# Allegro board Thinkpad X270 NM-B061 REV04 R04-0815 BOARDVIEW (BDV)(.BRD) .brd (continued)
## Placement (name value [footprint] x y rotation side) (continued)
R908  10K_0201_5%  [R_0201]  269.68 68.63 270 top
R951  10K_0201_5%  [R_0201]  283.45 47.74 180 top
R1119  0_0402_5%  [R_0402]  105.49 78.99 0 top
R1219  2.2K_0201_5%  [R_0201]  283.64 57.85 180 top
R1235  0_0201_5%  [R_0201]  267.43 68.03 90 top
R1236  0_0201_5%  [R0201_SHORT]  268.59 68.05 90 top
R1237  0_0201_5%  [R0201_SHORT]  266.9 67.17 180 top
R1238  0_0201_5%  [R0201_SHORT]  266.85 68.05 90 top
R1239  10K_0201_5%  [R_0201]  266.32 66.48 0 top
R1867  10K_0201_5%  [R_0201]  285.87 49.39 180 bottom
R1868  4.7K_0201_5%  [R_0201]  281.22 46.75 0 top
R1869  100K_0201_5%  [R_0201]  282.5 46.11 90 top
R1875  4.7K_0402_5%  [R_0402]  35.39 70.19 90 top
R1877  4.7K_0402_5%  [R_0402]  35.8 73.34 0 top
R1897  4.7K_0402_5%  [R_0402]  36.26 71.11 270 top
R1899  4.7K_0402_5%  [R_0402]  36.71 72.45 180 top
R2378  2.2K_0201_5%  [R_0201]  50.95 72.45 0 top
R2379  2.2K_0201_5%  [R_0201]  50.95 71.82 0 top
R2481  22K_0201_5%  [R_0201]  283.11 46.11 90 top
R2500  4.7K_0402_5%  [R_0402]  46.92 74.79 90 top
R2512  27K_0201_5%  [R_0201]  37.4 66.54 180 top
R2515  4.99K_0201_1%  [R_0201]  46.03 75.29 270 top
R2516  1M_0402_5%  [R_0402]  45.53 64.52 90 top
R2517  1M_0402_5%  [R_0402]  40.32 64.34 90 top
R2523  4.7K_0402_5%  [R_0402]  49.72 76.31 90 top
R2524  4.7K_0402_5%  [R_0402]  48.78 77.23 270 top
R2526  4.7K_0402_5%  [R_0402]  48.7 74.54 90 top
R2527  4.7K_0402_5%  [R_0402]  36.89 75.45 270 top
R2528  4.7K_0402_5%  [R_0402]  37.78 74.54 90 top
R2529  4.7K_0402_5%  [R_0402]  35.11 75.45 270 top
R2530  4.7K_0402_5%  [R_0402]  36 74.54 90 top
R2531  4.7K_0402_5%  [R_0402]  49.72 75.45 270 top
R2561  4.7K_0402_5%  [R_0402]  40.83 75.45 270 top
R2562  4.7K_0402_5%  [R_0402]  39.94 74.54 90 top
R2572  100K_0402_1%  [R_0402]  278.66 44.64 90 top
R2574  100K_0201_5%  [R_0201]  241.22 66.48 180 top
R2745  10K_0201_5%  [R_0201]  113.97 86.09 0 bottom
R2746  10K_0201_5%  [R_0201]  239.68 59.16 270 top
R2747  10K_0201_5%  [R_0201]  251.25 59.07 180 top
R2750  0_0201_5%  [R_0201]  237.5 61.98 270 top
R9083  0.01_0603_LE_1%  [R_0603_LE]  33.86 64.41 90 bottom
R9084  100K_0402_5%  [R_0402]  26.24 63.72 0 top
R9085  100K_0402_5%  [R_0402]  28.93 63.72 180 top
R9087  4.7K_0402_5%  [R_0402]  24.18 65.73 270 bottom
R9089  0_0201_5%  [R_0201]  23.29 65.73 270 bottom
R9090  10K_0402_5%  [R_0402]  27.97 65.02 180 top
R9091  4.7K_0402_5%  [R_0402]  31.54 62.84 180 bottom
R9093  4.7K_0402_5%  [R_0402]  32.38 62.84 0 bottom
R9095  0_0402_5%  [R0402_SHORT]  23.95 67.14 180 bottom
R9096  4.7K_0402_5%  [R_0402]  32.79 68.85 90 top
R9097  4.99K_0402_1%  [R_0402]  26.13 72.97 90 bottom
R9098  4.7K_0402_5%  [R_0402]  29.72 70.58 0 top
R9100  4.7K_0402_5%  [R_0402]  27.26 75.73 270 bottom
R9102  4.7K_0402_5%  [R_0402]  27.02 73.89 270 bottom
R9103  0_0402_5%  [R_0402]  17.18 55.26 180 bottom
R9104  0_0402_5%  [R_0402]  17.18 56.12 180 bottom
R9105  0_0402_5%  [R_0402]  16.87 57.04 180 bottom
R9106  4.7K_0402_5%  [R_0402]  22.42 70.1 0 bottom
R9107  4.7K_0402_5%  [R_0402]  22.42 69.19 0 bottom
R9108  2M_0402_1%  [R_0402]  15.63 50.76 180 top
R9109  0_0402_5%  [R_0402]  16.87 57.92 180 bottom
R9110  2M_0402_1%  [R_0402]  14.69 51.7 0 top
R9111  0_0402_5%  [R_0402]  17.18 53.48 180 bottom
R9112  4.7K_0402_5%  [R_0402]  32.84 67.28 180 top
R9113  4.7K_0402_5%  [R_0402]  29.72 69.36 0 top
R9114  0_0402_5%  [R_0402]  17.18 54.34 180 bottom
R9115  0_0402_5%  [R_0402]  16.87 58.79 180 bottom
R9116  4.7K_0402_5%  [R_0402]  26.34 69.66 180 top
R9117  4.7K_0402_5%  [R_0402]  26.35 70.54 180 top
R9118  0_0402_5%  [R_0402]  16.87 59.65 180 bottom
R9121  180_0402_1%  [R_0402]  16.42 33.59 270 top
R9123  180_0402_1%  [R_0402]  16.42 30.14 270 top
R9125  180_0402_1%  [R_0402]  16.42 31.86 270 top
R9127  180_0402_1%  [R_0402]  16.42 28.26 270 top
R9129  1M_0201_5%  [R_0201]  51.53 69.91 180 top
R9130  4.7K_0402_5%  [R_0402]  43.42 65.34 0 top
R9131  4.7K_0402_5%  [R_0402]  44.33 64.45 180 top
R9133  0_0201_5%  [R_0201]  110.97 72.45 180 bottom
R9134  10K_0201_5%  [R_0201]  131.86 70.19 180 top
R9135  10K_0201_5%  [R_0201]  131.81 67.35 180 top
R9136  10K_0201_5%  [R_0201]  131.87 71.03 180 top
R9137  10K_0201_5%  [R_0201]  131.89 68.14 180 top
R10071  0_0201_5%  [R0201_SHORT]  268 68.03 90 top
R10076  0_0603_5%  [R_0603]  276.31 54.53 90 top
R10079  0_0603_5%  [R0603_SHORT]  281.56 67.22 0 top
R10082  0_0402_5%  [R_0402]  286.27 66.46 180 top
R10088  1M_0201_5%  [R_0201]  253.69 58.46 0 top
R10089  1M_0201_5%  [R_0201]  253.81 57.3 90 top
R10090  1M_0201_5%  [R_0201]  254.36 57.3 90 top
R10095  100K_0201_5%  [R_0201]  266.9 65.9 180 top
R10096  0_0402_5%  [R0402_SHORT]  283.25 58.7 90 top
R10097  0_0402_5%  [R0402_SHORT]  284.92 64.07 180 top
R10132  200K_0201_1%  [R_0201]  284.34 53.89 180 top
R10133  100K_0402_1%  [R_0402]  284.89 51.55 180 top
R10141  100K_0201_5%  [R_0201]  235.31 85.14 90 top
R10197  0.01_0603_LE_1%  [R_0603_LE]  266.81 65.16 270 top
R10198  0.01_0603_LE_1%  [R_0603_LE]  266.84 59.56 90 top
R10199  0.01_0603_LE_1%  [R_0603_LE]  269.6 55.14 90 top
R10200  0.01_0603_LE_1%  [R_0603_LE]  280.83 72.83 270 top
R10201  0.01_0603_LE_1%  [R_0603_LE]  280.83 70.23 90 top
R10202  0.01_0603_LE_1%  [R_0603_LE]  283.07 70.79 270 top
R10203  0.01_0603_LE_1%  [R_0603_LE]  267.76 53.07 0 top
R10243  0_0201_5%  [R_0201]  13.12 47.27 270 bottom
R10244  0_0201_5%  [R_0201]  13.67 47.27 270 bottom
R10245  0_0201_5%  [R_0201]  14.23 47.27 270 bottom
R10246  0_0201_5%  [R_0201]  14.79 47.27 270 bottom
R10248  4.7K_0402_5%  [R_0402]  29.72 65.78 180 top
R10250  4.7K_0402_5%  [R_0402]  32.26 64.48 180 top
R10251  10K_0201_5%  [R_0201]  231.22 87.15 90 top
R10252  33_0201_5%  [R_0201]  251.25 62.7 180 top
R10253  0_0402_5%  [R_0402]  14.45 50.64 180 bottom
R10254  0_0402_5%  [R_0402]  14.45 49.75 180 bottom
R10255  0_0402_5%  [R_0402]  14.45 51.53 180 bottom
R10256  0_0402_5%  [R_0402]  14.45 52.42 180 bottom
R10320  33_0201_5%  [R_0201]  271.77 116.4 0 top
R10321  100_0201_5%  [R_0201]  270.77 113.44 90 top
R10324  10_0201_5%  [R_0201]  261.28 56.79 180 top
RA8  0_0402_5%  [R0402_SHORT]  290.7 61.69 270 top
RA9  0_0402_5%  [R0402_SHORT]  292.61 44.47 90 top
RA22  100K_0201_5%  [R_0201]  285.28 47.92 0 bottom
RA25  470K_0201_5%  [R_0201]  283.97 45.32 90 top
RA35  0_0201_5%  [R_0201]  283.97 62.42 0 top
RA36  0_0201_5%  [R_0201]  284.24 57.23 90 top
RA37  0_0201_5%  [R_0201]  277.33 54.18 90 top
RA39  0_0201_5%  [R_0201]  279.97 55.82 0 top
RA49  22K_0201_5%  [R_0201]  286.8 46.35 90 top
RA50  22K_0201_5%  [R_0201]  285.01 49.64 90 top
RA124  47K_0201_5%  [R_0201]  267.06 57.94 0 top
RA125  0_0402_5%  [R0402_SHORT]  284.92 63.18 180 top
RA126  0_0402_5%  [R0402_SHORT]  284.13 58.71 90 top
RA163  3.3_0402_5%  [R_0402]  267.65 58.66 180 top
RA290  200K_0201_1%  [R_0201]  277.29 44.54 0 top
RC1  24.9_0201_1%  [R_0201]  77.68 85.29 270 top
RC2  100K_0201_5%  [R_0201]  101.74 78.05 0 top
RC3  100K_0201_5%  [R_0201]  101.31 79.7 0 top
RC4  100K_0201_5%  [R_0201]  110.72 82.51 0 bottom
RC5  100K_0201_5%  [R_0201]  104.7 83.15 0 top
RC8  100K_0201_5%  [R_0201]  59.6 52.26 180 top
RC9  10K_0201_5%  [R_0201]  58.64 54.58 0 top
RC10  470_0201_5%  [R_0201]  88.62 54.47 180 top
RC11  121_0201_1%  [R_0201]  98.69 61.71 270 top
RC12  80.6_0201_1%  [R_0201]  100.64 61.15 270 top
RC13  100_0201_1%  [R_0201]  99.96 61.15 270 top
RC14  1K_0201_5%  [R_0201]  68.94 94.37 90 bottom
RC15  1K_0201_5%  [R_0201]  71.82 93.14 90 bottom
RC16  510_0201_5%  [R_0201]  68.74 93.43 180 bottom
RC17  49.9_0201_1%  [R_0201]  99.27 70.81 270 top
RC18  49.9_0201_1%  [R_0201]  99.86 70.81 270 top
RC19  49.9_0201_1%  [R_0201]  68.74 83.63 90 top
RC20  49.9_0201_1%  [R_0201]  70.01 84.09 0 top
RC21  51_0201_5%  [R_0201]  72.4 93.15 90 bottom
RC22  8.2K_0201_5%  [R_0201]  103.01 63.32 270 bottom
RC23  10K_0201_5%  [R_0201]  110.47 86.63 0 bottom
RC24  1K_0201_5%  [R_0201]  114.6 80.99 0 top
RC25  499_0201_1%  [R_0201]  114.6 78.68 0 top
RC26  499_0201_1%  [R_0201]  114.6 79.23 0 top
RC27  4.7K_0201_5%  [R_0201]  114.6 79.79 0 top
RC28  4.7K_0201_5%  [R_0201]  114.6 80.4 0 top
RC29  8.2K_0201_5%  [R_0201]  104.15 63.32 270 bottom
RC30  22_0201_5%  [R_0201]  106.21 63.3 270 bottom
RC31  0_0402_5%  [R0402_SHORT]  105.47 63.3 270 bottom
RC32  10K_0201_5%  [R_0201]  112.42 78.24 0 bottom
RC33  10K_0201_5%  [R_0201]  112.42 77.69 0 bottom
RC34  1K_0201_5%  [R_0201]  104.19 70.45 0 top
RC35  0_0201_5%  [R_0201]  102.21 75.84 180 top
RC36  1K_0201_5%  [R_0201]  95.39 59.49 270 top
RC37  0_0603_5%  [R_0603]  94.44 58.61 90 top
RC38  1K_0201_5%  [R_0201]  95.35 60.16 0 top
RC39  33_0201_5%  [R_0201]  96.24 59.22 0 bottom
RC40  33_0201_5%  [R_0201]  96.43 62.18 90 bottom
RC41  33_0201_5%  [R_0201]  96.42 59.81 90 bottom
RC42  33_0201_5%  [R_0201]  95.09 62.5 180 bottom
RC43  200_0201_1%  [R_0201]  104.3 77.99 0 top
RC44  10K_0201_5%  [R_0201]  104.2 91.92 90 bottom
RC45  10K_0201_5%  [R_0201]  103.62 91.92 90 bottom
RC47  10K_0201_5%  [R_0201]  110.47 86.04 0 bottom
RC48  113_0201_1%  [R_0201]  104.78 79.14 180 top
RC49  100_0201_1%  [R_0201]  103.84 85.41 270 top
RC51  0_0201_5%  [R_0201]  114.28 73.96 90 bottom
RC52  0_0201_5%  [R_0201]  113.7 73.96 90 bottom
RC53  0_0201_5%  [R_0201]  113.12 73.96 90 bottom
RC54  0_0201_5%  [R_0201]  114.89 73.96 90 bottom
RC55  1M_0201_5%  [R_0201]  86.72 91.29 90 bottom
RC56  0_0201_5%  [R_0201]  87.28 91.29 90 bottom
RC57  2.7K_0402_0.5%  [R_0402]  94.87 82.29 270 top
RC58  10M_0201_5%  [R_0201]  114.56 73.94 270 top
RC59  33_0201_5%  [R_0201]  142 69.04 270 bottom
RC60  33_0201_5%  [R_0201]  142 67.26 90 bottom
RC62  1M_0201_5%  [R_0201]  99.22 59.52 270 top
RC64  10K_0201_5%  [R_0201]  100.67 63.3 270 bottom
RC65  0_0201_5%  [R_0201]  106 92.91 270 bottom
RC66  0_0201_5%  [R_0201]  97.6 61.11 90 bottom
RC67  0_0201_5%  [R_0201]  97.82 62.28 90 bottom
RC68  0_0201_5%  [R_0201]  100.14 71.6 90 top
RC69  1K_0201_5%  [R_0201]  100.09 62.71 90 bottom
RC70  4.7K_0201_5%  [R_0201]  100.09 62.08 270 bottom
RC71  0_0201_5%  [R_0201]  286.89 65.93 0 bottom
RC72  10K_0201_5%  [R_0201]  71.76 94.7 270 top
RC73  10K_0201_5%  [R_0201]  69.17 94.16 90 top
RC74  0_0603_5%  [R0603_SHORT]  91.44 84.92 0 top
RC75  100_0201_1%  [R_0201]  89.72 84.96 90 top
RC76  56_0201_5%  [R_0201]  71.17 94.32 180 bottom
RC77  100_0201_1%  [R_0201]  71.18 93.14 90 bottom
RC79  220_0201_5%  [R_0201]  70.6 93.73 270 bottom
RC82  100_0201_1%  [R_0201]  89.16 85.55 270 top
RC85  0.01_0603_LE_1%  [R_0603_LE]  94.61 94.75 0 top
RC86  100_0201_1%  [R_0201]  93 73.06 180 top
RC87  100_0201_1%  [R_0201]  95.01 83.05 180 top
RC88  100_0201_1%  [R_0201]  62.71 83.64 270 bottom
RC90  100_0201_1%  [R_0201]  93.61 73.55 270 top
RC91  100_0201_1%  [R_0201]  95.18 84.06 90 top
RC92  100_0201_1%  [R_0201]  62.71 84.25 90 bottom
RC95  0_0603_5%  [R0603_SHORT]  100.36 95.94 270 top
RC96  0_0603_5%  [R0603_SHORT]  93.6 91.56 90 bottom
RC97  0_0402_5%  [R_0402]  102.34 82.39 90 top
RC98  0_0603_5%  [R0603_SHORT]  94.15 75.38 90 top
RC99  0_0603_5%  [R0603_SHORT]  94.85 79.13 180 top
RC100  1K_0201_5%  [R_0201]  65.29 93.7 270 bottom
RC101  1K_0201_5%  [R_0201]  67.45 93.48 270 bottom
RC102  1K_0201_5%  [R_0201]  70.52 85.61 180 top
RC103  49.9_0201_1%  [R_0201]  73.72 84.63 180 top
RC104  0_0201_5%  [R0201_SHORT]  106.79 63.28 0 bottom
RC107  0_0201_5%  [R0201_SHORT]  68.88 70.08 90 top
RC110  100K_0201_5%  [R_0201]  69.35 93.13 90 bottom
RC111  1K_0201_5%  [R_0201]  188.72 60.46 0 top
RC112  100_0201_5%  [R_0201]  188.24 58.91 0 top
RC116  1.5K_0201_1%  [R_0201]  170.96 58.66 0 top
RC117  2.2K_0402_1%  [R_0402]  55.25 72.83 90 top
RC118  1K_0201_5%  [R_0201]  170.32 58.7 270 top
RC122  1K_0201_5%  [R_0201]  102.7 58.64 0 top
RC123  20K_0201_5%  [R_0201]  97.22 60.95 90 top
RC124  20K_0201_5%  [R_0201]  97.1 60.21 180 top
RC125  10K_0201_5%  [R_0201]  123.73 71.25 270 top
RC126  3.3K_0201_5%  [R_0201]  122.69 72.31 90 top
RC127  3.3K_0201_5%  [R_0201]  118.96 74.57 270 bottom
RC128  33_0201_5%  [R_0201]  123.15 70.66 90 top
RC129  33_0201_5%  [R_0201]  118.36 75.17 0 bottom
RC130  33_0201_5%  [R_0201]  118.96 76.43 90 bottom
RC131  33_0201_5%  [R_0201]  122.13 72.31 90 top
RC132  33_0201_5%  [R_0201]  124.44 72.9 270 top
RC133  33_0201_5%  [R_0201]  118.35 74.57 270 bottom
RC134  20K_0201_5%  [R_0201]  113.97 100.54 0 bottom
RC135  10K_0201_5%  [R_0201]  105.17 92.33 90 bottom
RC137  51_0201_5%  [R_0201]  188.74 54.98 0 top
RC138  51_0201_5%  [R_0201]  188.82 57.85 180 top
RC139  51_0201_5%  [R_0201]  188.82 57.29 180 top
RC140  1K_0201_5%  [R_0201]  118.37 76.43 90 bottom
RC141  1K_0201_5%  [R_0201]  123.28 72.9 270 top
RC142  51_0201_5%  [R_0201]  75.24 92.85 90 bottom
RC149  0_0201_5%  [R_0201]  188.82 56.6 180 top
RC150  1K_0201_5%  [R_0201]  110.25 70.3 180 bottom
RC151  1K_0201_5%  [R_0201]  111.95 68.85 180 bottom
RC152  1K_0201_5%  [R_0201]  101.02 75.84 180 top
RC153  10K_0201_5%  [R_0201]  100.72 72.44 90 top
RC154  0_0201_5%  [R0201_SHORT]  89.34 54.44 270 top
RC155  0_0201_5%  [R_0201]  112.7 100.55 0 bottom
RC156  1K_0201_5%  [R_0201]  112.99 77.11 180 bottom
RC157  0_0201_5%  [R0201_SHORT]  112.84 75.71 180 bottom
RC158  1.5K_0201_1%  [R_0201]  105.42 60.82 180 top
RC159  47K_0402_1%  [R_0402]  105.01 59.91 270 top
RC161  100_0201_1%  [R_0201]  69.94 93.13 90 bottom
RC162  100K_0201_5%  [R_0201]  103.5 83.2 0 top
RC164  10K_0402_5%  [R_0402]  188.27 59.7 0 top
RC166  0_0201_5%  [R0201_SHORT]  57.17 72.83 0 top
RC167  10K_0201_5%  [R_0201]  32.48 55.83 90 top
RC168  10K_0201_5%  [R_0201]  32.49 55.2 270 top
RC169  100K_0201_5%  [R_0201]  56.88 52.19 180 top
RD1  0_0201_5%  [R_0201]  84.88 30.93 90 top
RD2  0_0201_5%  [R_0201]  86.84 30.93 90 top
RD3  0_0201_5%  [R_0201]  83.12 30.71 90 top
RD4  0_0201_5%  [R0201_SHORT]  85.52 31.51 270 top
RD5  0_0201_5%  [R0201_SHORT]  86.2 31.51 270 top
RD6  0_0201_5%  [R0201_SHORT]  82.53 31.29 270 top
RD7  1K_0201_1%  [R_0201]  67.37 29.55 180 top
RD8  2_0201_1%  [R_0201]  62.8 26.91 90 top
RD9  1K_0201_1%  [R_0201]  66.53 27.29 90 top
RD10  24.9_0201_1%  [R_0201]  62.24 28.74 270 top
RD11  240_0201_1%  [R_0201]  55.81 28.4 90 top
RD12  0_0201_5%  [R0201_SHORT]  87.93 34.81 180 top
RJ2  -  [JUMP_43X118]  84.85 57.67 90 top
RJ3  -  [JUMP_43X79]  109.03 101.66 0 top
RJ4  -  [JUMP_43X79]  124.99 77.66 0 top
RJ5  -  [JUMP_43X79]  248.12 63.87 0 top
RL1  10K_0201_5%  [R_0201]  216.54 66.7 90 top
RL2  10K_0201_5%  [R_0201]  216.74 68.79 0 top
RL3  0_0201_5%  [R0201_SHORT]  216.72 70.01 0 top
RL4  100_0201_1%  [R_0201]  207.27 71.76 0 top
RL5  100_0201_1%  [R_0201]  207.27 70.6 0 top
RL6  4.7K_0201_5%  [R_0201]  216.74 68.15 0 top
RL7  10K_0201_5%  [R_0201]  207.29 69.61 0 top
RL8  10K_0201_5%  [R_0201]  207.31 67.6 0 top
RL9  100_0201_1%  [R_0201]  217.33 71.41 180 top
RL10  1K_0201_5%  [R_0201]  207.27 71.18 0 top
RL11  3.01K_0201_1%  [R_0201]  216.75 73.49 270 top
RL12  330_0402_5%  [R_0402]  284.03 120.43 180 top
RL13  330_0402_5%  [R_0402]  280.19 134.59 0 top
RT1  540_0402NEW_30%_PRF15BB541NB6RC  [R_0402]  229.12 99.94 180 top
RT2  540_0402NEW_30%_PRF15BB541NB6RC  [R_0402]  193.35 63.79 180 bottom
RT3  540_0402NEW_30%_PRF15BB541NB6RC  [R_0402]  160.12 102.15 0 top
RT4  540_0402NEW_30%_PRF15BB541NB6RC  [R_0402]  143.42 108.27 180 top
RT5  540_0402NEW_30%_PRF15BB541NB6RC  [R_0402]  146.19 81.77 270 bottom
RT6  540_0402NEW_30%_PRF15BB541NB6RC  [R_0402]  173.01 79.36 0 bottom
RT7  540_0402NEW_30%_PRF15BB541NB6RC  [R_0402]  192.39 71.92 90 bottom
RT8  540_0402NEW_30%_PRF15BB541NB6RC  [R_0402]  117.79 59.98 0 bottom
RX55  0_0603_5%  [R_0603]  50.61 74.95 270 bottom
S1  SPVR310100_4P  [SW_SPVR310100_4P]  288.05 60.86 0 bottom
S2  SPVT210101_4P  [SW_SPVT210101_4P]  266 101.91 180 bottom
S3  SKRPABE010_4P  [SW_SKRPABE010_4P]  259.58 138.39 270 bottom
ST1  HOLEA  [PAD_C6P5D2P8]  205.55 85.16 0 top
ST2  HOLEA  [PAD_C6P5D2P8]  234.85 97.16 0 top
ST3  HOLEA  [PAD_C5P6D3P4]  255.55 98.11 0 top
ST4  HOLEA  [PAD_CT5P6B6P6D3P4]  279.75 50.71 0 top
ST5  HOLEA  [PAD_CT6P5B7P5D3P4]  183 90.21 0 top
T1  BOTH_NA0069R-LF  [BOTH_NA0069R-LF_24P]  269.22 119.49 90 bottom
TC5  Test_Point_40MIL  [TPC40]  22.53 63.31 0 bottom
TP1  Test_Point_40MIL  [TPC40]  96.55 58.99 0 top
TP2  Test_Point_40MIL  [TPC40]  93.87 61.74 0 top
TP5  TESTPAD  [TPC12]  245.62 86.55 0 top
TP6  TESTPAD  [TPC12]  226.69 71.12 0 top
TP7  TESTPAD  [TPC12]  221.04 71.18 0 top
TP8  TESTPAD  [TPC12]  244.79 70.93 0 top
TP9  TESTPAD  [TPC12]  245.34 65.96 0 top
TP10  TESTPAD  [TPC12]  223.1 71.46 0 top
TP11  TESTPAD  [TPC12]  228.38 71.03 0 top
TP12  TESTPAD  [TPC12]  226.73 68.87 0 top
TP14  TESTPAD  [TPC12]  222.06 72.28 0 top
TP15  TESTPAD  [TPC12]  231.99 85.15 0 top
TP16  TESTPAD  [TPC12]  174.02 90.13 0 top
TP17  Test_Point_40MIL  [TPC40]  64.09 54.37 0 top
TP18  Test_Point_40MIL  [TPC40]  71.31 70.42 0 top
TP19  Test_Point_40MIL  [TPC40]  72.58 73.34 0 top
TP20  Test_Point_40MIL  [TPC40]  69.33 76.14 0 top
TP21  Test_Point_40MIL  [TPC40]  70.72 76.19 0 top
TP22  Test_Point_40MIL  [TPC40]  56.83 78.42 0 top
TP23  Test_Point_40MIL  [TPC40]  56.83 77.02 0 top
TP24  Test_Point_40MIL  [TPC40]  73.97 73.34 0 top
TP25  Test_Point_40MIL  [TPC40]  75.37 73.34 0 top
TP26  Test_Point_40MIL  [TPC40]  76.76 72.86 0 top
TP27  Test_Point_40MIL  [TPC40]  76.39 71.44 0 top
TP28  Test_Point_40MIL  [TPC40]  74.99 71.44 0 top
TP29  Test_Point_40MIL  [TPC40]  45.7 32.37 0 top
TP30  Test_Point_40MIL  [TPC40]  44.18 32.37 0 top
TP31  Test_Point_40MIL  [TPC40]  64.65 30.62 0 top
TP32  Test_Point_40MIL  [TPC40]  64.75 33.08 0 top
TP37  Test_Point_40MIL  [TPC40]  71.87 84.53 0 top
TP38  Test_Point_40MIL  [TPC40]  245.7 84.82 0 top
TP39  Test_Point_40MIL  [TPC40]  250.55 84.77 0 top
TP40  Test_Point_40MIL  [TPC40]  260.82 83.2 0 top
TP41  Test_Point_40MIL  [TPC40]  66.4 94.47 180 bottom
TP42  Test_Point_40MIL  [TPC40]  258.3 103.8 0 top
TP43  Test_Point_40MIL  [TPC40]  256.95 103.39 0 top
TP44  Test_Point_40MIL  [TPC40]  252.46 103.69 0 top
TP45  Test_Point_40MIL  [TPC40]  264.25 109.64 0 top
TP46  Test_Point_40MIL  [TPC40]  249.23 104.96 0 top
TP47  Test_Point_40MIL  [TPC40]  249.74 101.74 0 top
TP48  Test_Point_40MIL  [TPC40]  255.63 103.92 0 top
TP49  Test_Point_40MIL  [TPC40]  250.86 103.85 0 top
TP50  Test_Point_40MIL  [TPC40]  58.23 78.42 0 top
TP51  Test_Point_40MIL  [TPC40]  208.49 75.58 0 top
TP52  Test_Point_40MIL  [TPC40]  207.58 68.59 0 top
TP56  TESTPAD  [TPC12]  152.53 97.45 180 bottom
TP57  Test_Point_32MIL  [TPC32]  22.71 64.99 0 top
TP58  PAD  [TPC12]  27.03 45.88 0 top
TP77  PAD  [TPC12]  18.52 48.76 0 top
TP78  PAD  [TPC12]  19.44 46.72 0 top
TP80  Test_Point_40MIL  [TPC40]  57.16 75.3 0 top
TP82  Test_Point_32MIL  [TPC32]  21.41 61.26 0 top
TP83  Test_Point_40MIL  [TPC40]  225.26 85.46 0 top
TP84  Test_Point_40MIL  [TPC40]  247.3 70.01 0 top
TP85  Test_Point_16MIL  [TPC16]  104.57 95.42 180 bottom
TP88  Test_Point_16MIL  [TPC16]  105.94 69.99 0 top
TP90  Test_Point_16MIL  [TPC16]  52.48 67.4 180 bottom
TP91  Test_Point_16MIL  [TPC16]  67.03 54.3 0 top
TP92  Test_Point_16MIL  [TPC16]  52.53 65.32 180 bottom
TP94  Test_Point_16MIL  [TPC16]  64.21 84.83 180 bottom
TP95  Test_Point_16MIL  [TPC16]  62.79 85.92 180 bottom
TP96  Test_Point_16MIL  [TPC16]  110.14 61.26 180 bottom
TP97  Test_Point_16MIL  [TPC16]  111.96 60.65 180 bottom
U1  SKYLAKE-U_BGA1356  [SKYLAKE-U_BGA_1356P-T]  107.34 89.12 0 bottom
U5  TPS65982DAZQZR_BGA96  [TPS65982DAZQZR_BGA_96P]  29.48 52.27 270 top
U7  -  [TC7SB385FU_SSOP5]  222.06 50.46 0 top
U12  TPS2546RTER_QFN16_3X3  [TPS2546RTER_QFN16_4X4]  274.01 81.43 270 top
U13  G517F1P81U_MSOP8  [TPS2069DGNR_MSOP8]  18.88 24.09 90 top
U14  PI3L720ZHE+CX_TQFN42_9X3P5  [PI3L720ZHELFCX_TQFN42_9X3P5]  214.05 84.61 0 top
U15  RTS5232S-GR_QFN32_4X4  [RTS5232-GR_QFN32_4X4]  283.68 85.3 90 top
U16  MEC1653  [MEC1653TMP-TN_WFBGA_169P-T]  237.13 73.27 180 top
U17  -  [KX023-1025_LGA16_3X3]  169.31 91.2 0 top
U19  -  [TC7SB385FU_SSOP5]  249.31 95.33 90 top
U20  -  [TC7SB385FU_SSOP5]  244.09 95.45 0 top
U21  ThinkEngine_2  [BD4178GSW_BGA_80P-T]  254.55 72.73 180 top
U23  -  [TPS2553DBVR_SOT23-6]  15.69 38.45 180 top
U24  -  [PI2EQX862XUAEX_TQFN18_2X2]  238.29 50.68 270 top
U25  -  [PI2EQX862XUAEX_TQFN18_2X2]  231.56 50.96 270 top
U26  SLB9670VQ2.0_VQFN32_5X5  [SLB9670VQ2P0_VQFN32_5X5]  127.47 60.64 270 top
U27  -  [TC7SB385FU_SSOP5]  217.64 47.81 90 top
U36  SN74AUP1G07DCKR_SC-70  [NL17SG07DFT2G_SC-88A5]  55.36 54.31 270 top
U147  -  [PS8349BQFN66GTR-A0_QFN66_5X10]  48.15 72.39 270 top
U163  -  [TC7SPB9306TU_UF6]  248.87 56.2 0 top
U183  -  [PS8743BQFN40GTR-B0_QFN40_4X6]  26.75 71.54 270 bottom
U184  -  [TC7SB385FU_SSOP5]  133.07 71.07 270 top
U185  -  [TC7SB385FU_SSOP5]  133.07 68.61 270 top
U186  -  [W25Q80BLSNIG_SO8]  30.74 57.37 90 top
U187  FPF2281BUCX-F130_WLCSP12  [FPF2281BUCX-F130_WLCSP_12P]  8.01 65.74 0 top
U191  -  [74AVCH2T45GD_XSON8_3X2]  238.79 55.52 90 top
U193  -  [TPD8S300_QFN20_3X3]  14.02 45.6 90 top
UA1  ALC3268-CG_QFN56_7X7  [ALC298-CG_QFN56_7X7]  269.28 64.94 0 top
UC3  -  [TC7SG17FE_SON5]  139.91 68.11 90 bottom
UC4  -  [SLG59M1470VTR_FC-TDFN9_1P5X2]  114.46 98.98 180 bottom
UC5  -  [W25Q128FVSIQ_SO8]  126.88 70.78 180 bottom
UL1  -  [WGI219LM-QREF-A0_QFN48_6X6]  215.26 67.99 90 top
UNK46J BARCODE  -  []  253.35 52.34 90 bottom
Y1  24MHZ_10PF_8Y24000011  [Y_8Y24000011_4P]  88.72 91.82 90 bottom
Y2  32.768KHZ 9PF 20PPM 9H03280012  [Y_9H03200042_2P]  116.6 75.23 270 top
YL1  25MHZ_18PF_8Y25000004  [Y_8Y25000004_4P]  219.44 73.43 90 top

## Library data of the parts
C1 C3 C5 C6 C19-C21 C36 C73 C75 C77-C79 C90-C92 C107 C109 C122 C131 C138 C140 C155-C157 C159 C186 C188-C193 C198 C199 C201-C207 C238 C260 C261 C264 C265 C268 C269 C271-C275 C278 C280 C281 C292-C294 C296 C298-C300 C302 C303 C305 C502 C535-C545 C547 C549 C551 C552 C555-C559 C561 C564 C796 C800 C809 C811-C815 C817 C818 C821-C824 C830 C852 C900 C1416 C1417 C2544 C2545 C2571 C2575 C2587 C2729 C2730 C8333 C8356 C9130 C9134-C9140 C9142 C9463 C9464 C9487 CA5 CA37 CA44-CA47 CA52-CA56 CA73 CA117 CA119 CA122 CA127 CA142 CA243 CA913 CC5 CC14 CC15 CC18-CC24 CC31 CC55 CC64-CC67 CC69-CC71 CD1-CD10 CD13 CD14 CD34 CD36 CL16 CL17 PC3 PC5 PC10 PC11 PC13 PC16 PC18-PC27 PC83 PC102 PC132-PC135 PC137 PC144 PC147 PC148 PC150 PC156 PC157 PC160-PC162 PC165 PC170 PC181 PC183 PC203 PC204 PC207-PC209 PC212 PC213 PC218 PC219 PC224 PC301 PC302 PC306 PC311 PC319 PC405 PC409 PC410 PC414 PC416 PC417 PC420 PC422 PC423 PC425 PC428 PC431 PC439 PC469 PC526 PC718 PC790 = CAP NP
C2 C83-C86 C125 C128 C135 C174 C181 C217 C219 C220 C241-C254 C304 C417-C422 C2764 C2765 C9112 C9113 CC32-CC34 CC42 CC68 CC74-CC76 CD25 CD28 CD29 CD31 CD46 PC225 = CAP NP: signal model: CAP_NP_C_0201_0.1U_0201_6.3V6K_0.1U_0201_6.3V6K
C4 C9-C14 C97-C100 C108 C110 C143-C150 C152 C194 C195 C208 C230 C232 C235 C236 C262 C263 CC72 CC73 = CAP NP: signal model: CAP_NP_C_0201_0.1U_0201_10V6K_0.1u_0201_10V6K
C7 C196 C197 C816 = C 0.1UF_25V_1005_X7R_K
C8 = C 1UF_25V_1608_X7R_K
C30 C301 C306 C308 C310 C318 C2503 C2522-C2531 C2543 C2546 C2572 C2573 C2576 C8337-C8355 C8358-C8361 C9146 C9197 CA124 CD32 PC401 = CAP NP: signal model: CAP_NP_C_0201_0.1U_0201_6.3V6-K_0.1U_0201_6.3V6-K
C76 C124 C126 C127 C129 C130 C180 C185 C209 C211-C213 C215 C216 C229 C256 C282-C285 C290 CC17 CC38 CD26 CD50 PC4 PC6-PC9 PC14 PC15 PC17 PC28 PC50-PC54 PC82 PC84 PC128 PC129 PC131 PC136 PC138-PC143 PC145 PC146 PC149 PC151-PC155 PC158 PC159 PC163 PC164 PC166 PC167 PC180 PC182 PC205 PC206 PC210 PC211 PC214 PC215 PC221 PC226-PC231 PC303-PC305 PC307-PC310 PC312 PC316 PC317 PC320 PC321 PC402-PC404 PC406-PC408 PC411-PC413 PC418 PC419 PC421 PC424 PC426 PC427 PC429 PC430 PC432-PC438 PC449-PC451 PC453 PC463-PC468 PC470 PC471 PC480 PC498 PC499 PC522-PC525 PC527-PC529 PC712-PC716 PC723 PC738-PC741 PC743 PC746 PC756 PC776 PC784-PC786 PC788 PC789 PC791-PC795 PC801 PC803 PR802 = P_CAP NP
C101 C178 C234 = CAP WP
C111-C115 C117-C121 C123 CL7 CL11 CL12 CL14 = CAP NP: signal model: CAP_NP_C_0201_0.1U_0201_6.3V6K_0.1U_0201_6.3V6K; room: LAN
C116 C257-C259 C500 CL5 CL8 CL10 = CAP NP: room: LAN
C132 C137 C139 C141 C142 CL9 = CAP NP: signal model: CAP_NP_C_0201_0.1U_0201_6.3V6K_0.1U_0201_6.3V6K; room: Media Card
C133 C134 C136 C297 CW1 CW2 = CAP NP: room: Media Card
C158 C160-C168 C255 C266 C267 C277 C279 C307 C309 C311 CD33 CD35 CD37 = CAP NP: room: KBC
C169-C171 C184 R168 = CAP NP: signal model: CAP_NP_C_0201_0.1U_0201_6.3V6K_0.1U_0201_6.3V6K; room: KBC
C172 = P_CAP NP: room: KBC
C173 = CAP NP: room: KBC; signal model: CAP_NP_C_0201_0.1U_0201_6.3V6K_0.1U_0201_6.3V6K
C175-C177 C286-C289 CC25-CC27 CC36 CC37 CC39 CC40 CC44-CC49 CL6 CL13 PC440-PC448 PC452 PC454-PC459 PC461 PC462 PC472-PC479 PC481-PC485 PC488-PC497 PC506-PC508 PC510-PC517 PC530-PC535 PC537-PC540 PC719-PC722 PC724 = CAP NP: room: KB
C187 = CAP NP: room: CPU; signal model: CAP_NP_C_0201_0.1U_0201_10V6K_0.1u_0201_10V6K
C200 = C 2.2UF_25V_1608_X5R_K
C312 = CAP NP: signal model: CAP_NP_C_0201_0.1U_0201_6.3V6K_0.1U_0201_6.3V6K; room: CPU
C333 C546 C553 C2574 C9141 = P_CAP NP_0
C709 C810 CD27 CD30 = CAP NP: room: 27
CC10-CC13 CC28-CC30 CC35 CC41 CC43 CC50-CC54 CC56-CC63 CC78-CC97 CD11 CD12 CD15-CD23 CD38-CD45 CD51 = CAP NP: room: CPU
CC99 CD47-CD49 = CAP NP: signal model: CAP_NP_C_0201_0.1U_0201_6.3V6-K_0.1U_0201_6.3V6-K; room: CPU
CD24 PC80 PC220 PC222 PC223 PC314 PC460 PC487 PC500-PC503 = P_CAP WP
CL1-CL4 PC717 = P_CAP NP: signal model: P_CAP_NP_C_0402_0.1U_0402_16V7-_0.1U_0402_16V7-K
D1 D2 D16 D22 D29 D30 D34 D36-D39 D41-D44 D46 D47 D58-D65 D705 D708 D709 D714 D739 D740 D744 DC1 PD32 PD102 PD301 = RB521CS-30GT2RA_VMN2-2
D13 D54 = AOZ8904CIL_SOT23-6
D15 D51-D53 D87 D88 = AZ1043-04F.R7G_DFN2510P10E10-9
D17 D19 = RCLAMP0502BPTCT_SC75-3
D18 = FTZ6.8EGT148_SC-74A5
D24 D94 D99 D710 DA5 = RSB5.6SGTE61_SC-79-2-2
D25 D253 PD10-PD18 PD31 = DAN222MGT2L_VMD3
D26 D55-D57 = DF2S6P8UFS_1-1L1A2
D28 = RB521CS-30GT2RA_VMN2-2: room: KBC
D31 D35 = 1SS400CST2RA_VMN2-2
D70 = P_EDZVT2R15B_EMD2-2
D707 PD1 PD2 = P_1SS400CMT2R_VMN2M2
D711 = PESD5V0U2BT_SOT23-3
DC2-DC5 = RB520CS-30GT2RA_VMN2-2
DL1 DL2 = CM1293A-04SO_SC-74-6
E_L1-E_L3 E_L7-E_L9 L7-L10 L12-L17 = EXC24CH900U_4P
F1 F2 F7 F41 = 3A_32V_ERBRD3R00X
F3 F4 F8 F9 F14 F15 F40 F42 F152 PF5-PF9 PF11 = 0.5A_32V_ERBRD0R50X
F5 F6 F16 = 2A_32V_ERBRD2R00X
F10 F11 = 1A_32V_ERBRD1R00X: room: KB
FD1-FD6 = FM_2
FL3 FL5 = L: signal model: L_TDK_MMZ1005Y152CT_2P_MMZ1005Y_MMZ1005Y152CT_2P
FL6 = L: room: LAN
H1-H16 ST1-ST5 = HOLE
J1 = I-PEX_20525-040E-02
J3 = SINGA_2RJ3047-108411F
J4 = TYCO_5
J5 = HRS_DF12L3P014DP0P5V86A
J8 = MOLEX_0
J10 J11 = I-PEX_20374-030E-31
J12 = TE_2041180-2
J15 = HIGHS_FC5AF071-3151H
J16 J26 = HIGHS_BT5P0201-1001H
J17 = TE_2129525-2
J19 = SINGA_2SJ3052-012111F
J21 = FOX_AS0A826-H4RB-7H
J22 = TYCO_2199230-3
J23 = ALPS_SCDAAA0604
J25 = JAE_SF11V006S4C_0
J32 = TYCO_3
J34 J42 = SINGA_2UB3908-000101F
J37 = JAE_FL10S012HA1
J38 = JAE_FL10F032HA2R3000
J41 = FCI_4
J43 = FOX_QJ111A1-R000H1-7H
JTYC1 = HIGHS_UB11126-A5A0B-1H
LA11-LA14 PL102 PL103 PL404-PL408 PL410 = L
PC81 PC216 PC217 PC313 PC486 PC536 PC745 PC787 PC802 = P_CAP NP: room: CPU_CORE
PC737 PC783 = P_CAP NP: signal model: CAP_NP_C_0201_0.1U_0201_6.3V6K_0.1U_0201_6.3V6K
PD4 PD701 = P_RB751V-40_SOD323-2
PD5 = AZ5425-01F_DFN1006P2E2
PD7-PD9 = DF2S6.8UFS_1-1L1A2
PD30 = RB520SM-30T2R_EMD2-2
PF2 = 5A_32V_S1206-H-5.0A
PF3 PF4 = P_10A_24V_TR-3216FF10-R
PJ1 = MOLEX_78048-0543
PJ2 = P_JST_SM05BLBTAKSTDN2T-HF
PJ3 = P_FOX_BBP27BY-B4801-7H
PJ4 PJ201-PJ204 PJ301-PJ304 PJ701-PJ703 PJ711 PJ712 PJ715 PJ716 RJ2-RJ5 = P_JUMP_43X118
PL1 PL101 PL201 PL202 PL301 PL401 PL402 PL702-PL704 = P_L
PQ2 PQ6 PQ7 PQ18 PQ20 PQ103 PQ108 = SI7121DN-T1-GE3_POWERPAK-8-5
PQ5 PQ9 PQ10 PQ41 PQ104-PQ107 PQ109 Q5 Q16 Q29 Q30 Q36 Q170 Q171 QC2 QC3 = 2SK3541_VMT3
PQ8 = P_DTA014EMT2L_VMT3
PQ11 = P_2N7002KDWH_SOT363-6
PQ12 PQ13 PQ17 PQ19 PQ112 PQ113 = P_SIS406DN-T1-GE3_PAK1212-8-5
PQ14 PQ110 PQ111 = P_TPCA8059-H_PPAK56-8-5_0
PQ15 = P_2N7002KW_SOT323-3
PQ21 PQ23 = P_SSM6J402TU_UF6
PQ22 PQ24 = P_DTC015EMT2L_VMT3
PQ37 = P_AON6248_DFN8-5
PQ42 = P_2SCR512P5T100_MPT3
PQ201-PQ204 PQ301 PQ302 = AON7408L_DFN8-5
PR1 PR15 PR17-PR19 PR24 PR46 PR79 PR82-PR84 PR87-PR89 PR95-PR99 PR101 PR133 PR135 PR138 PR145-PR148 PR150 PR152 PR154 PR165 PR168 PR169 PR190 PR210 PR211 PR219 PR220 PR305 PR401 PR403 PR407 PR408 PR410 PR414 PR418-PR421 PR423 PR424 PR428 PR430 PR443 PR446-PR448 PR451 PR452 PR457 PR469 PR721 PR723 PR724 PR753 PR765 PR766 R46 R101 R340 R341 R401 R439 R450 R460 R483 R489 R532 R571 R572 R574 R576 R600 R601 R678-R682 R798 R801 R819 R851 R852 R862 R908 R951 R1119 R1219 R1239 R1867 R1869 R1875 R1877 R1897 R1899 R2378 R2379 R2500 R2512 R2523 R2524 R2526-R2531 R2561 R2562 R2574 R2745-R2747 R9087 R9090 R9091 R9093 R9096 R9098 R9100 R9102-R9118 R9130 R9131 R9134-R9137 R10132 R10243-R10246 R10248 R10250 R10251 R10253-R10256 R10321 RA22 RA124 RA290 RC12 RC16 RC76 RC79 RC103 RC164 = P_R
PR2 PR3 PR6-PR14 PR20-PR23 PR25-PR45 PR77 PR78 PR134 PR136 PR139 PR142 PR144 PR151 PR153 PR155 PR156 PR158 PR163 PR164 PR167 PR170-PR172 PR179 PR196 PR197 PR216-PR218 PR303 PR307 PR308 PR411 PR412 PR417 PR425 PR427 PR433-PR435 PR437-PR439 PR441 PR442 PR444 PR445 PR449 PR453 PR456 PR470 PR473 PR762 PR801 R7 R10 R52 R108 R179 R180 R307 R310 R311 R313 R316 R318-R320 R322-R325 R370 R392 R395 R414 R443 R457 R458 R484 R490 R508 R509 R537 R546 R547 R677 R711-R716 R721-R724 R727-R729 R742 R743 R780-R786 R790 R791 R799 R849 R850 R1868 R2481 R2515-R2517 R2572 R9084 R9085 R9097 R9121 R9123 R9125 R9127 R9129 R10076 R10088-R10090 R10095 R10133 R10324 RA25 RA35-RA37 RA39 RA49 RA50 RA163 RC48 RC57 RC97 RC116 RC117 RC158 RC159 RD7 RD8 RD11 = R
PR16 PR91 PR92 PR214 PR215 PR221 PR222 PR301 PR306 PR406 PR409 PR416 PR436 PR450 PR463-PR468 PR475 PR477 PR718 PR749 PR750 PR755 R169 R173 R237 R244-R247 R260 R278 R304 R355 R384 R385 R387 R393 R396 R437 R461 R462 R573 R725 R9095 R10079 RA8 RA9 RC74 RC95 RC96 RC98 RC99 RC154 RC157 RC166 RD12 = R-SHORT
PR90 = P_R: room: VSB
PR102 PR103 R140 R142 R160 R161 R165 R167 R192 R206 R207 R230 R309 R312 R354 R430 R433-R435 R904 R9133 R10141 RC9 RC11 RC13 RC21-RC23 RC25-RC29 RC32 RC33 RC36-RC43 RC49 RC51-RC54 RC56 RC64-RC71 RC125 RC137-RC139 RC142 RC149 RC155 RC167 RC168 RL4 RL5 = R_0: room: CPU
PR137 PR140 PR149 PR160 PR161 PR302 PR304 PR402 PR404 PR405 PR413 PR415 PR429 PR432 PR440 PR474 PR708 PR738 PR751 PR761 R1-R4 R51 R89 R90 R104 R109 R110 R113 R116-R118 R120 R127 R226 R227 R231-R233 R238-R243 R248 R249 R251 R252 R254-R259 R261-R266 R268-R271 R273-R275 R280 R281 R283 R285 R286 R288-R290 R292 R294-R297 R299 R301 R303 R305 R306 R314 R372 R373 R376 R377 R382 R389 R390 R397-R399 R405-R408 R428 R436 R485 R486 R602 R702 R703 R789 R802 R2750 R9089 R10252 R10320 RC1-RC5 RC10 RC17-RC20 RC44 RC45 RC47 RC59 RC60 RC75 RC77 RC82 RC86-RC88 RC90-RC92 RC100-RC102 RC110-RC112 RC118 RC122-RC124 RC126-RC135 RC153 RC161 RC162 RL9 RL12 RL13 RX55 = R_0
PR141 PR157 PR162 PR166 R423-R426 R1235 = P_R: signal model: P_R_R_0201_0_0201_5%_0_0201_5%
PR208 PR209 PR309 PR312 PR462 PR709 = P_R-SHORT
PR212 PR213 PR311 PR455 PR461 PR476 PR722 PR760 PR803 = P_R: room: CPU_CORE
PRT401 PRT402 PRT404 PRT405 = P_MURAT_NCP03WF104F05RL
PRT403 = P_MURAT_NCP03WL224E05RL
PU4 = P_APL3542AQBI-TRG_TDFN10_0
PU5 = P_TPS61041DRVR_SON6_2X2
PU6 = P_NCP431AISNT1G_SOT23-3
PU101 = P_BQ25700RSNR_QFN32_4X4
PU201 = P_TPS51285BRUKR_WQFN20_3X3
PU301 = P_TPS51716RUKR_WQFN20_3X3
PU401 = P_NCP81208MNTXG_QFN48_6X6
PU402 PU403 PU405 = P_NCP81382MNTXG_QFN39-31_6X4
PU701 PU706 = P_RT8068AZQW_WDFN10_1
PU702 = P_TPS51367RVER_QFN28_3P5X4P5
Q1 Q19 Q21 Q23 Q24 Q33 = TPCF8002_2-3U1A
Q4 Q28 = MMBT3904_SOT23-3
Q7 = 2SK3541_VMT3: room: KBC
Q8 = DTC115EMGT2L_VMT3: room: KBC
Q9-Q13 Q25 = 2SC5658GT2LR_VMT3: room: KBC
Q14 = RW1E014SNT2R_WEMT6_0
Q17 = P_SSM6K210FE_2-2N1A
Q20 Q26 = TMP_160302
Q34 Q35 = P_SIP32451DB-T2-GE1_WCSP4
Q39 Q40 Q50 Q197 Q226-Q228 Q263 QA7 = LSK3541G1ET2L_VMT3
Q41 = RTM002P02GT2L_VMT3
Q60 = TPS22918DBVR_SOT23-6
Q175 QA8 = DTC115EMGT2L_VMT3
Q199 QC1 = DTC115TMT2L_VMT3
Q266 = P_TPCF8004_2-3U1S
R5 R6 R15 R66 R67 R124-R126 R128-R139 R143 R146-R149 R151-R156 R158 R159 R164 R166 R171 R172 R174 R175 R181-R189 R193-R198 R200-R202 R205 R208-R211 R234-R236 R342-R353 R356-R363 R365 R368 R369 R374 R375 R383 R394 R402-R404 R413 R440 RC8 RC30 RC169 = R_0: room: KBC
R8 R9 = R_0: signal model: R-SHORT_R0201_SHORT_0_0201_5%_0_0201_5%
R11 R12 R92-R95 R102 R103 R105 R106 R144 R145 RC31 RC104 RC107 RD4-RD6 RL3 = R-SHORT: signal model: R-SHORT_R0201_SHORT_0_0201_5%_0_0201_5%
R91 R96-R100 R409 RC14 RC15 RC24 RC34 RC72 RC73 RC140 RC141 RC150-RC152 RC156 RL1 RL2 RL6-RL8 RL10 = R_0: room: LAN
R111 = R: signal model: R_R_0201_0_0201_5xxxxxxxx%_0_0201_5%
R112 = R_0: room: Media Card
R163 = P_R: room: KBC
R170 = R 4.53K_1%_0603: room: KBC
R176 RC55 RC62 = R 1M_5%_0603: signal model: R_1M_5%_0603_R_0201_1M_0201_5%_1M_0201_5%; room: CPU
R177 R178 R427 = R 1M_5%_0603: room: CPU
R212-R225 R277 = R_0: room: KB
R276 = R 1.78M_1%_1005
R279 = R 1.24M_1%_1005
R284 = R 2K_5%_0603
R302 R9083 R10197-R10203 RC85 = P_R: room: CHARGER
R315 R317 = R: signal model: R_R_0402_113_0402_1%_113_0402_1%
R415 R416 = R: signal model: P_R_R_0201_0_0201_5%_0_0201_5%
R431 R10082 = R: signal model: R_R_0402_0_0402_5%_0_0402_5%
R441 R707 R708 R10096 R10097 RA125 RA126 = R-SHORT: signal model: R_R_0402_0_0402_5%_0_0402_5%
R1236-R1238 R10071 = R-SHORT: signal model: P_R_R_0201_0_0201_5%_0_0201_5%
RC35 = R_0: room: CPU; signal model: R-SHORT_R0201_SHORT_0_0201_5%_0_0201_5%
RC58 = R 10M_5%_0603: room: CPU
RD1-RD3 = R: room: CPU
RD9 = R: room: LAN
RD10 = R: room: KBC
RL11 = R 3.01K_1%_0603: room: LAN
RT1-RT8 = 540_0402NEW_30%_PRF15BB541NB6RC
S1 = SPVR110100_4P
S2 = SPVT210101_4P
S3 = SKRPABE010_4P
T1 = BOTH_NA0069R-LF
TC5 TP1 TP2 TP17-TP32 TP37-TP52 TP80 TP83 TP84 = TEST_POINT_40MIL
TP5-TP12 TP14-TP16 TP56 = PAD_0: room: KBC
TP57 TP82 = Test_Point_32MIL
TP58 TP77 TP78 = PAD_0: room: VGA
TP85 TP88 TP90-TP92 TP94-TP97 = Test_Point_16MIL
U1 = SKYLAKE-U_BGA1356
U5 = TPS65982DAZQZR_BGA96
U7 U19 U20 U27 U184 U185 = TC7SB385FU_SSOP5
U12 = TPS2543RTER_QFN16_3X3
U13 = TPS2069DGNR_MSOP8
U14 = PI3L720ZHE+CX_TQFN42_9X3P5
U15 = RTS5232-GR_QFN32_0
U16 = IC MEC1653
U17 = KX023-1025_LGA16_3X3
U21 = IC THINKENGINE_2
U23 = TPS2553DBVR_SOT23-6
U24 U25 = PI2EQX862XUAEX_TQFN18_2X2
U26 = SLB9670VQ2.0_VQFN32_5X5
U36 = NL17SG07DFT2G_SC-88A5
U147 = PS8349BQFN66GTR-A0_QFN66_5X10
U163 = TC7SPB9306TU_UF6
U183 = PS8743BQFN40GTR-B0_QFN40_4X6
U186 = W25Q80BLSNIG_SO8
U187 = FPF2281BUCX-F130_WLCSP12
U191 = 74AVCH2T45GD_XSON8_3X2
U193 = TPD8S300_QFN20_3X3
UA1 = ALC298-CG_QFN56_7X7
UC3 = TC7SG17FE_SON5
UC4 = P_SLG59M1470VTR_FC-TDFN9_1P5X2
UC5 = W25Q128FVSIQ_SO8
UL1 = WGI219LM-QREF-A0_QFN48_6X6
Y1 = 24MHZ_10PF_8Y24000011
Y2 = 32.768KHZ_12.5PF_9H03200042
YL1 = 25MHZ_18PF_8Y25000004

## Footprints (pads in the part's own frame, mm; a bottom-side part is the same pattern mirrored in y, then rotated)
1SS400CMT2R_VMN2M2
  rect 0.559x0.457 smd: 1(0,0.475) 2(0,-0.475)
1SS400CST2RA_VMN2-2
  rect 0.457x0.559 smd: 1(0,0) 2(0.95,0)
2N7002KDWH_SOT363-6
  oval 0.356x0.889 smd: 1(0,0) 2(0.65,0) 3(1.3,0) 4(1.3,1.6) 5(0.65,1.6) 6(0,1.6)
2N7002WT1G_SC-70-3
  oval 0.711x0.889 smd: 1(0,0) 2(0.65,1.9) 3(-0.65,1.9)
2SC5658GT2LR_VMT3
  oval 0.508x0.457 smd: 1(0,0)
  oval 0.406x0.457 smd: 2(-0.4,-1.15) 3(0.4,-1.15)
2SCR512P5T100_MPT3
  rect 0.66x1.702 smd: 1(0,0) 3(3,0)
  custom 0.425x0.425 smd: 2(1.5,1.295)
2SK3541_VMT3
  oval 0.508x0.457 smd: 1(0,0)
  oval 0.406x0.457 smd: 2(-0.4,-1.15) 3(0.4,-1.15)
74AVCH2T45GD_XSON8_3X2
  oval 0.305x1.143 smd: 1(0,0.2)
  oval 0.305x1.041 smd: 2(0.5,0.149) 3(1,0.149) 4(1.5,0.149) 5(1.5,2.749) 6(1,2.749) 7(0.5,2.749) 8(0,2.749)
ALC298-CG_QFN56_7X7
  oval 0.94x0.305 smd: 1(0,0) 2(0,-0.4) 3(0,-0.8) 4(0,-1.2) 5(0,-1.6) 6(0,-2) 7(0,-2.4) 8(0,-2.8) 9(0,-3.2) 10(0,-3.6) 11(0,-4) 12(0,-4.4) 13(0,-4.8) 14(0,-5.2) 29(6.95,-5.2) 30(6.95,-4.8) 31(6.95,-4.4) 32(6.95,-4) 33(6.95,-3.6) 34(6.95,-3.2) 35(6.95,-2.8) 36(6.95,-2.4) 37(6.95,-2) 38(6.95,-1.6) 39(6.95,-1.2) 40(6.95,-0.8) 41(6.95,-0.4) 42(6.95,0)
  oval 0.305x0.94 smd: 15(0.875,-6.075) 16(1.275,-6.075) 17(1.675,-6.075) 18(2.075,-6.075) 19(2.475,-6.075) 20(2.875,-6.075) 21(3.275,-6.075) 22(3.675,-6.075) 23(4.075,-6.075) 24(4.475,-6.075) 25(4.875,-6.075) 26(5.275,-6.075) 27(5.675,-6.075) 28(6.075,-6.075) 43(6.075,0.875) 44(5.675,0.875) 45(5.275,0.875) 46(4.875,0.875) 47(4.475,0.875) 48(4.075,0.875) 49(3.675,0.875) 50(3.275,0.875) 51(2.875,0.875) 52(2.475,0.875) 53(2.075,0.875) 54(1.675,0.875) 55(1.275,0.875) 56(0.875,0.875)
  rect 4.597x4.597 smd: 57(3.475,-2.6)
ALPS_SCDAAA0900_12P
  round 0.787 hole 0.787 unplated: (-8.477,-27.805)
  oval 1.092x0.787 hole 1.092x0.787 unplated: (15.723,-27.805)
  oval 0.711x1.829 smd: 1(0,0) 2(1,0) 3(2,0) 4(3,0) 5(4,0) 6(7.601,0) 7(9.601,0) 8(10.601,0) 9(-1,0) 10(8.601,0) 11(11.601,0) 12(12.601,0)
  rect 2.388x1.829 smd: 13(-8.132,0)
  rect 1.397x1.829 smd: 14(15.898,0)
  rect 1.092x2.794 smd: 15(17.626,-28.205) 16(-10.379,-28.205)
AON6248_DFN8-5
  oval 0.508x0.66 smd: 1(0,0) 2(1.27,0) 3(2.54,0) 4(3.81,0)
  custom 1.15x1.15 smd: 5(1.905,2.755)
AON7408L_DFN8-5
  oval 0.356x0.508 smd: 1(0,0) 2(0.65,0) 3(1.3,0) 4(1.95,0)
  custom 0.57x0.57 smd: 5(0.975,1.91)
AOZ8904CIL_SOT23-6
  oval 0.635x0.787 smd: 1(0,0) 2(0.95,0) 3(1.9,0) 4(1.9,2.4) 5(0.95,2.4) 6(0,2.4)
APL3542AQBI-TRG_TDFN10_3X3
  oval 0.711x0.406 smd: 1(0,0) 2(0,-0.508) 3(0,-1.016) 4(0,-1.524) 5(0,-2.032) 6(2.794,-2.032) 7(2.794,-1.524) 8(2.794,-1.016) 9(2.794,-0.508) 10(2.794,0)
  rect 1.575x2.438 smd: 11(1.397,-1.016)
AZ1043-04FPR7G_DFN2510P10E10
  oval 0.33x0.762 smd: 1(0,0) 2(0.5,0) 4(1.5,0) 5(2,0) 6(2,0.875) 7(1.5,0.875) 8(0.5,0.875) 9(0,0.875)
  oval 0.406x1.549 smd: 3(1,0.437)
AZ5425-01F_DFN1006P2E2
  rect 0.559x0.61 smd: 1(0,0) 2(0.85,0)
BD4178GSW_BGA_80P-T
  round 0.343 smd: A1(0,0) A2(0.8,0) A3(1.6,0) A4(2.4,0) A5(3.2,0) A6(4,0) A7(4.8,0) A8(5.6,0) A9(6.4,0) B1(0,-0.8) B2(0.8,-0.8) B3(1.6,-0.8) B4(2.4,-0.8) B5(3.2,-0.8) B6(4,-0.8) B7(4.8,-0.8) B8(5.6,-0.8) B9(6.4,-0.8) C1(0,-1.6) C2(0.8,-1.6) C3(1.6,-1.6) C4(2.4,-1.6) C5(3.2,-1.6) C6(4,-1.6) C7(4.8,-1.6) C8(5.6,-1.6) C9(6.4,-1.6) D1(0,-2.4) D2(0.8,-2.4) D3(1.6,-2.4) D4(2.4,-2.4) D5(3.2,-2.4) D6(4,-2.4) D7(4.8,-2.4) D8(5.6,-2.4) D9(6.4,-2.4) E1(0,-3.2) E2(0.8,-3.2) E3(1.6,-3.2) E4(2.4,-3.2) E6(4,-3.2) E7(4.8,-3.2) E8(5.6,-3.2) E9(6.4,-3.2) F1(0,-4) F2(0.8,-4) F3(1.6,-4) F4(2.4,-4) F5(3.2,-4) F6(4,-4) F7(4.8,-4) F8(5.6,-4) F9(6.4,-4) G1(0,-4.8) G2(0.8,-4.8) G3(1.6,-4.8) G4(2.4,-4.8) G5(3.2,-4.8) G6(4,-4.8) G7(4.8,-4.8) G8(5.6,-4.8) G9(6.4,-4.8) H1(0,-5.6) H2(0.8,-5.6) H3(1.6,-5.6) H4(2.4,-5.6) H5(3.2,-5.6) H6(4,-5.6) H7(4.8,-5.6) H8(5.6,-5.6) H9(6.4,-5.6) J1(0,-6.4) J2(0.8,-6.4) J3(1.6,-6.4) J4(2.4,-6.4) J5(3.2,-6.4) J6(4,-6.4) J7(4.8,-6.4) J8(5.6,-6.4) J9(6.4,-6.4)
BOTH_NA0069R-LF_24P
  oval 0.787x1.549 smd: 1(0,0) 2(1.27,0) 3(2.54,0) 4(3.81,0) 5(5.08,0) 6(6.35,0) 7(7.62,0) 8(8.89,0) 9(10.16,0) 10(11.43,0) 11(12.7,0) 12(13.97,0) 13(13.97,8.95) 14(12.7,8.95) 15(11.43,8.95) 16(10.16,8.95) 17(8.89,8.95) 18(7.62,8.95) 19(6.35,8.95) 20(5.08,8.95) 21(3.81,8.95) 22(2.54,8.95) 23(1.27,8.95) 24(0,8.95)
BQ25700RSNR_QFN32_4X4
  oval 0.203x0.787 smd: 1(0,0) 2(0.4,0) 3(0.8,0) 4(1.2,0) 5(1.6,0) 6(2,0) 7(2.4,0) 8(2.8,0) 17(2.8,4) 18(2.4,4) 19(2,4) 20(1.6,4) 21(1.2,4) 22(0.8,4) 23(0.4,4) 24(0,4)
  oval 0.787x0.203 smd: 9(3.4,0.6) 10(3.4,1) 11(3.4,1.4) 12(3.4,1.8) 13(3.4,2.2) 14(3.4,2.6) 15(3.4,3) 16(3.4,3.4) 25(-0.6,3.4) 26(-0.6,3) 27(-0.6,2.6) 28(-0.6,2.2) 29(-0.6,1.8) 30(-0.6,1.4) 31(-0.6,1) 32(-0.6,0.6)
  rect 2.794x2.794 smd: 33(1.4,2)
C_0201
  rect 0.33x0.305 smd: 1(0,0) 2(0.584,0)
C_0402
  rect 0.508x0.559 smd: 1(0,0) 2(0.914,0)
C_0603
  rect 0.635x0.889 smd: 1(0,0) 2(1.397,0)
C_0805
  rect 0.813x1.397 smd: 1(0,0) 2(1.702,0)
C_1808
  rect 1.041x2.311 smd: 1(0,0) 2(4.35,0)
C_B2
  rect 1.346x2.692 smd: 1(0,0) 2(-2.75,0)
C_D2
  rect 2.388x2.794 smd: 1(0,0) 2(6.4,0)
CM1293A-04SO_SC-74-6
  oval 0.711x0.991 smd: 1(0,0) 2(0.95,0) 3(1.9,0) 4(1.9,2.4) 5(0.95,2.4) 6(0,2.4)
CYNTE_HMMB25201T-1R0MSR_2P
  rect 0.787x2.007 smd: 1(0,0) 2(2,0)
CYNTE_PCMB063T-1R0MS_2P
  rect 2.159x3.505 smd: 1(0,0) 2(5.85,0)
CYNTE_PCMB063T-2R2MS_2P
  rect 2.159x3.505 smd: 1(0,0) 2(5.85,0)
CYNTE_PCMB063T-R47MS3R675_2P
  rect 2.362x3.505 smd: 1(0,0) 2(6.05,0)
CYNTE_PCMC063T-1R0MN_2P
  rect 1.854x3.505 smd: 1(0,0) 2(5.55,0)
CYNTE_PCME063T-R15MS0R907_2P
  rect 2.362x3.505 smd: 1(0,0) 2(6.05,0)
CYNTE_PH041H-1R0MS_2P
  rect 1.295x3.81 smd: 1(0,0) 2(3.1,0)
DAN222MGT2L_VMD3
  oval 0.508x0.457 smd: 1(0,0)
  oval 0.406x0.457 smd: 2(-0.4,-1.15) 3(0.4,-1.15)
DF2S6P8UFS_1-1L1A2
  rect 0.406x0.406 smd: 1(0,0) 2(1,0)
DTA014EMT2L_VMT3
  rect 0.508x0.457 smd: 1(0,0)
  rect 0.406x0.457 smd: 2(-0.4,-1.15) 3(0.4,-1.15)
DTC015EMT2L_VMT3
  rect 0.508x0.457 smd: 1(0,0)
  rect 0.406x0.457 smd: 2(-0.4,-1.15) 3(0.4,-1.15)
DTC115EMGT2L_VMT3
  oval 0.508x0.457 smd: 1(0,0)
  oval 0.406x0.457 smd: 2(-0.4,-1.15) 3(0.4,-1.15)
DTC115TMT2L_VMT3
  oval 0.508x0.457 smd: 1(0,0)
  oval 0.406x0.457 smd: 2(-0.4,-1.15) 3(0.4,-1.15)
EDZVT2R15B_EMD2-2
  rect 0.61x0.787 smd: 1(0,0) 2(1.7,0)
F_ERBRD0R50X
  rect 0.483x0.508 smd: 1(0,0) 2(1.025,0)
F_ERBRD1R00X
  rect 0.483x0.508 smd: 1(0,0) 2(1.025,0)
F_ERBRD2R00X
  rect 0.483x0.508 smd: 1(0,0) 2(1.025,0)
F_ERBRD3R00X
  rect 0.483x0.508 smd: 1(0,0) 2(1.025,0)
F_S1206-H-5P0A
  rect 1.194x2.388 smd: 1(0,0) 2(3.2,0)
F_TR-3216FF10-R
  rect 0.991x1.803 smd: 1(0,0) 2(2.5,0)
FCI_10051922-1810ELF_18P-T
  oval 0.305x0.787 smd: 1(0,0) 2(-0.5,0) 3(-1,0) 4(-1.5,0) 5(-2,0) 6(-2.5,0) 7(-3,0) 8(-3.5,0) 9(-4,0) 10(-4.5,0) 11(-5,0) 12(-5.5,0) 13(-6,0) 14(-6.5,0) 15(-7,0) 16(-7.5,0) 17(-8,0) 18(-8.5,0)
  rect 0.94x0.991 smd: 19(1.225,2.7) 20(-9.725,2.7)
FIDUCIAL_C40M80
  round 1.016 smd: 1(0,0)
FOX_AS0A826-H4RB-7H_260P-T
  round 1.092 hole 1.092 unplated: (-67.775,-4.1)
  round 1.6 hole 1.6 unplated: (1.025,-4.1)
  oval 0.406x1.854 smd: 1(0,0) 2(-0.25,-8.2) 3(-0.5,0) 4(-0.75,-8.2) 5(-1,0) 6(-1.25,-8.2) 7(-1.5,0) 8(-1.75,-8.2) 9(-2,0) 10(-2.25,-8.2) 11(-2.5,0) 12(-2.75,-8.2) 13(-3,0) 14(-3.25,-8.2) 15(-3.5,0) 16(-3.75,-8.2) 17(-4,0) 18(-4.25,-8.2) 19(-4.5,0) 20(-4.75,-8.2) 21(-5,0) 22(-5.25,-8.2) 23(-5.5,0) 24(-5.75,-8.2) 25(-6,0) 26(-6.25,-8.2) 27(-6.5,0) 28(-6.75,-8.2) 29(-7,0) 30(-7.25,-8.2) 31(-7.5,0) 32(-7.75,-8.2) 33(-8,0) 34(-8.25,-8.2) 35(-8.5,0) 36(-8.75,-8.2) 37(-9,0) 38(-9.25,-8.2) 39(-9.5,0) 40(-9.75,-8.2) 41(-10,0) 42(-10.25,-8.2) 43(-10.5,0) 44(-10.75,-8.2) 45(-11,0) 46(-11.25,-8.2) 47(-11.5,0) 48(-11.75,-8.2) 49(-12,0) 50(-12.25,-8.2) 51(-12.5,0) 52(-12.75,-8.2) 53(-13,0) 54(-13.25,-8.2) 55(-13.5,0) 56(-13.75,-8.2) 57(-14,0) 58(-14.25,-8.2) 59(-14.5,0) 60(-14.75,-8.2) 61(-15,0) 62(-15.25,-8.2) 63(-15.5,0) 64(-15.75,-8.2) 65(-16,0) 66(-16.25,-8.2) 67(-16.5,0) 68(-16.75,-8.2) 69(-17,0) 70(-17.25,-8.2) 71(-17.5,0) 72(-17.75,-8.2) 73(-18,0) 74(-18.25,-8.2) 75(-18.5,0) 76(-18.75,-8.2) 77(-19,0) 78(-19.25,-8.2) 79(-19.5,0) 80(-19.75,-8.2) 81(-20,0) 82(-20.25,-8.2) 83(-20.5,0) 84(-20.75,-8.2) 85(-21,0) 86(-21.25,-8.2) 87(-21.5,0) 88(-21.75,-8.2) 89(-22,0) 90(-22.25,-8.2) 91(-22.5,0) 92(-22.75,-8.2) 93(-23,0) 94(-23.25,-8.2) 95(-23.5,0) 96(-23.75,-8.2) 97(-24,0) 98(-24.25,-8.2) 99(-24.5,0) 100(-24.75,-8.2) 101(-25,0) 102(-25.25,-8.2) 103(-25.5,0) 104(-25.75,-8.2) 105(-26,0) 106(-26.25,-8.2) 107(-26.5,0) 108(-26.75,-8.2) 109(-27,0) 110(-27.25,-8.2) 111(-27.5,0) 112(-27.75,-8.2) 113(-28,0) 114(-28.25,-8.2) 115(-28.5,0) 116(-28.75,-8.2) 117(-29,0) 118(-29.25,-8.2) 119(-29.5,0) 120(-29.75,-8.2) 121(-30,0) 122(-30.25,-8.2) 123(-30.5,0) 124(-30.75,-8.2) 125(-31,0) 126(-31.25,-8.2) 127(-31.5,0) 128(-31.75,-8.2) 129(-32,0) 130(-32.25,-8.2) 131(-32.5,0) 132(-32.75,-8.2) 133(-33,0) 134(-33.25,-8.2) 135(-33.5,0) 136(-33.75,-8.2) 137(-34,0) 138(-34.25,-8.2) 139(-34.5,0) 140(-34.75,-8.2) 141(-35,0) 142(-35.25,-8.2) 143(-35.5,0) 144(-35.75,-8.2) 145(-38,0) 146(-38.25,-8.2) 147(-38.5,0) 148(-38.75,-8.2) 149(-39,0) 150(-39.25,-8.2) 151(-39.5,0) 152(-39.75,-8.2) 153(-40,0) 154(-40.25,-8.2) 155(-40.5,0) 156(-40.75,-8.2) 157(-41,0) 158(-41.25,-8.2) 159(-41.5,0) 160(-41.75,-8.2) 161(-42,0) 162(-42.25,-8.2) 163(-42.5,0) 164(-42.75,-8.2) 165(-43,0) 166(-43.25,-8.2) 167(-43.5,0) 168(-43.75,-8.2) 169(-44,0) 170(-44.25,-8.2) 171(-44.5,0) 172(-44.75,-8.2) 173(-45,0) 174(-45.25,-8.2) 175(-45.5,0) 176(-45.75,-8.2) 177(-46,0) 178(-46.25,-8.2) 179(-46.5,0) 180(-46.75,-8.2) 181(-47,0) 182(-47.25,-8.2) 183(-47.5,0) 184(-47.75,-8.2) 185(-48,0) 186(-48.25,-8.2) 187(-48.5,0) 188(-48.75,-8.2) 189(-49,0) 190(-49.25,-8.2) 191(-49.5,0) 192(-49.75,-8.2) 193(-50,0) 194(-50.25,-8.2) 195(-50.5,0) 196(-50.75,-8.2) 197(-51,0) 198(-51.25,-8.2) 199(-51.5,0) 200(-51.75,-8.2) 201(-52,0) 202(-52.25,-8.2) 203(-52.5,0) 204(-52.75,-8.2) 205(-53,0) 206(-53.25,-8.2) 207(-53.5,0) 208(-53.75,-8.2) 209(-54,0) 210(-54.25,-8.2) 211(-54.5,0) 212(-54.75,-8.2) 213(-55,0) 214(-55.25,-8.2) 215(-55.5,0) 216(-55.75,-8.2) 217(-56,0) 218(-56.25,-8.2) 219(-56.5,0) 220(-56.75,-8.2) 221(-57,0) 222(-57.25,-8.2) 223(-57.5,0) 224(-57.75,-8.2) 225(-58,0) 226(-58.25,-8.2) 227(-58.5,0) 228(-58.75,-8.2) 229(-59,0) 230(-59.25,-8.2) 231(-59.5,0) 232(-59.75,-8.2) 233(-60,0) 234(-60.25,-8.2) 235(-60.5,0) 236(-60.75,-8.2) 237(-61,0) 238(-61.25,-8.2) 239(-61.5,0) 240(-61.75,-8.2) 241(-62,0) 242(-62.25,-8.2) 243(-62.5,0) 244(-62.75,-8.2) 245(-63,0) 246(-63.25,-8.2) 247(-63.5,0) 248(-63.75,-8.2) 249(-64,0) 250(-64.25,-8.2) 251(-64.5,0) 252(-64.75,-8.2) 253(-65,0) 254(-65.25,-8.2) 255(-65.5,0) 256(-65.75,-8.2) 257(-66,0) 258(-66.25,-8.2) 259(-66.5,0) 260(-66.75,-8.2)
  rect 3.505x4.597 smd: 261(0.425,7.9) 262(-67.175,7.9)
FOX_BBP27BY-B4801-7H_7P-T
  round 1.499 hole 1.092: 1(0,0) 2(2,0) 3(6,0) 4(8,0) 5(10,0) 6(12,0) 7(14,0)
  oval 1.397x2.794 hole 0.991x2.388: 8(-3.1,0.2) 9(17.1,0.2)
FOX_QJ111A1-R000H1-7H_19P-TXX
  oval 0.787x0.864 hole 0.559: 1(0,0) 2(-0.5,-1.2) 3(-1,0) 4(-1.5,-1.2) 5(-2,0) 7(-3,0) 9(-4,0) 11(-5,0) 12(-5.5,-1.2) 13(-6,0) 14(-6.5,-1.2) 15(-7,0) 16(-7.5,-1.2) 17(-8,0) 18(-8.5,-1.2) 19(-9,0)
  oval 0.686x0.864 hole 0.559: 6(-2.5,-1.2) 8(-3.5,-1.2) 10(-4.5,-1.2)
  oval 1.6x2.311 hole 0.991x1.702: 20(-11.75,-0.7) 21(-13.5,7.7) 22(4.5,7.7) 23(2.75,-0.7)
FPF2281BUCX-F130_WLCSP_12P
  round 0.203 smd: A1(0,0) A2(0.4,0) A3(0.8,0) A4(1.2,0) B1(0,-0.4) B2(0.4,-0.4) B3(0.8,-0.4) B4(1.2,-0.4) C1(0,-0.8) C2(0.4,-0.8) C3(0.8,-0.8) C4(1.2,-0.8)
FTZ6P8EGT148_SC-74A5
  oval 0.787x0.991 smd: 1(0,0) 2(-2,0) 3(-2,2.4) 5(0,2.4)
  oval 0.61x0.991 smd: 4(-1,2.4)
HIGHS_BT5P0201-1001H_20P-T
  round 0.711 hole 0.711 unplated: (-5.55,-0.3) (1.05,-0.3)
  oval 0.406x1.702 smd: 1(0,0) 2(0,-3.6) 3(-0.5,0) 4(-0.5,-3.6) 5(-1,0) 6(-1,-3.6) 7(-1.5,0) 8(-1.5,-3.6) 9(-2,0) 10(-2,-3.6) 11(-2.5,0) 12(-2.5,-3.6) 13(-3,0) 14(-3,-3.6) 15(-3.5,0) 16(-3.5,-3.6) 17(-4,0) 18(-4,-3.6) 19(-4.5,0) 20(-4.5,-3.6)
  rect 0.787x1.803 smd: 21(1.7,-1.8) 22(-6.2,-1.8)
HIGHS_FC5AF071-3151H_7P
  oval 0.406x0.889 smd: 1(0,0) 2(0.5,0) 3(1,0) 4(1.5,0) 5(2,0) 6(2.5,0) 7(3,0)
  rect 0.406x1.194 smd: 8(-1,-2.7) 9(4,-2.7)
HIGHS_UB11126-A5A0B-1H_24P-T
  round 0.66 hole 0.66 unplated: (-0.7,0.01)
  oval 0.787x0.66 hole 0.787x0.66 unplated: (6.2,0.01)
  oval 0.406x0.787 smd: 1(0,0) 2(0.5,0) 3(1,0) 4(1.5,0) 5(2,0) 6(2.5,0) 7(3,0) 8(3.5,0) 9(4,0) 10(4.5,0) 11(5,0) 12(5.5,0)
  oval 1.143x0.66 hole 0.889x0.406: 13(5.95,-1.12) 24(-0.45,-1.12)
  round 0.635 hole 0.406: 14(5.25,-2.03) 15(4.45,-2.03) 16(4.05,-1.12) 17(3.6,-2.03) 18(3.15,-1.12) 19(2.35,-1.12) 20(1.9,-2.03) 21(1.45,-1.12) 22(1.05,-2.03) 23(0.25,-2.03)
  oval 0.991x2.007 hole 0.508x1.499: 25(-3.325,-5.79) 26(-3.325,-1.92) 33(8.825,-1.92) 34(8.825,-5.79)
  oval 0.991x1.6 hole 0.508x1.092: 27(-1.725,0.41) 32(7.225,0.41)
  rect 0.508x0.305 smd: 28(-0.45,0.7) 29(1.75,0.7) 30(3.75,0.7) 31(5.95,0.7)
HRS_DF12L3P014DP0P5V86A_14P-T
  round 0.61 hole 0.61 unplated: (-1.05,-0.3) (4.05,-0.3)
  oval 0.305x1.6 smd: 1(0,0) 2(0,-3.6) 3(0.5,0) 4(0.5,-3.6) 5(1,0) 6(1,-3.6) 7(1.5,0) 8(1.5,-3.6) 9(2,0) 10(2,-3.6) 11(2.5,0) 12(2.5,-3.6) 13(3,0) 14(3,-3.6)
  rect 0.787x1.803 smd: 15(-1.75,-1.8) 16(4.75,-1.8)
I-PEX_20374-030E-31_30P
  oval 0.203x1.194 smd: 1(0,0) 2(0.4,0) 3(0.8,0) 4(1.2,0) 5(1.6,0) 6(2,0) 7(2.4,0) 8(2.8,0) 9(3.2,0) 10(3.6,0) 11(4,0) 12(4.4,0) 13(4.8,0) 14(5.2,0) 15(5.6,0) 16(6,0) 17(6.4,0) 18(6.8,0) 19(7.2,0) 20(7.6,0) 21(8,0) 22(8.4,0) 23(8.8,0) 24(9.2,0) 25(9.6,0) 26(10,0) 27(10.4,0) 28(10.8,0) 29(11.2,0) 30(11.6,0)
  rect 1.397x2.007 smd: 31(-2.5,-1.37) 32(14.1,-1.37)
I-PEX_20525-040E-02_40P
  oval 0.305x0.889 smd: 1(0,0) 2(-0.4,0) 3(-0.8,0) 4(-1.2,0) 5(-1.6,0) 6(-2,0) 7(-2.4,0) 8(-2.8,0) 9(-3.2,0) 10(-3.6,0) 11(-4,0) 12(-4.4,0) 13(-4.8,0) 14(-5.2,0) 15(-5.6,0) 16(-6,0) 17(-6.4,0) 18(-6.8,0) 19(-7.2,0) 20(-7.6,0) 21(-8,0) 22(-8.4,0) 23(-8.8,0) 24(-9.2,0) 25(-9.6,0) 26(-10,0) 27(-10.4,0) 28(-10.8,0) 29(-11.2,0) 30(-11.6,0) 31(-12,0) 32(-12.4,0) 33(-12.8,0) 34(-13.2,0) 35(-13.6,0) 36(-14,0) 37(-14.4,0) 38(-14.8,0) 39(-15.2,0) 40(-15.6,0)
  rect 0.559x0.889 smd: 41(0.9,0.05) 42(-16.5,0.05)
  rect 0.711x1.295 smd: 43(2.645,0.8) 44(-18.245,0.8)
  rect 0.711x1.854 smd: 45(2.645,3.125) 46(-18.245,3.125)
  rect 0.559x0.559 smd: 47(-1.8,0.925) 48(-4.2,0.925) 49(-6.6,0.925) 50(-9,0.925) 51(-11.4,0.925) 52(-13.8,0.925)
JAE_FL10F012HA1R3000_12P-T
  round 0.991 hole 0.991 unplated: (-12.05,3.85) (1.05,3.85)
  oval 0.356x0.991 smd: 1(0,0) 2(-1,0) 3(-2,0) 4(-3,0) 5(-4,0) 6(-5,0) 7(-6,0) 8(-7,0) 9(-8,0) 10(-9,0) 11(-10,0) 12(-11,0)
  rect 1.499x1.499 smd: 13(2.5,4.15) 14(-13.5,4.15)
JAE_FL10F032HA2R3000_32P
  round 0.991 hole 0.991 unplated: (-1.05,-3.85) (16.55,-3.85)
  oval 0.356x0.991 smd: 1(0,0) 2(0.5,0) 3(1,0) 4(1.5,0) 5(2,0) 6(2.5,0) 7(3,0) 8(3.5,0) 9(4,0) 10(4.5,0) 11(5,0) 12(5.5,0) 13(6,0) 14(6.5,0) 15(7,0) 16(7.5,0) 17(8,0) 18(8.5,0) 19(9,0) 20(9.5,0) 21(10,0) 22(10.5,0) 23(11,0) 24(11.5,0) 25(12,0) 26(12.5,0) 27(13,0) 28(13.5,0) 29(14,0) 30(14.5,0) 31(15,0) 32(15.5,0)
  rect 1.499x1.499 smd: 33(-2.5,-4.15) 34(18,-4.15)
JAE_SF11V006S4C_9P-T
  oval 0.889x1.143 smd: 1(0,0) 2(2.54,0) 3(5.08,0) 4(7.62,0) 5(0,-15.33) 6(2.54,-15.33) 7(5.08,-15.33) 8(7.62,-15.33) 9(6.85,4.12)
  rect 1.448x3.099 smd: 10(11.65,-17.705) 13(-4.15,-17.705)
  rect 2.108x1.245 smd: 11(-1.175,3.82) 12(4.25,3.82)
JST_SM05BLBTAKSTDN2T-HF_5P-T
  oval 1.499x2.057 smd: 1(0,0) 5(5.45,0)
  oval 0.61x1.549 smd: 2(1.725,-1.1) 3(2.725,-1.1) 4(3.725,-1.1)
  rect 1.194x2.489 hole 0.508x0.991: 6(-2.375,-5.425) 7(7.825,-5.425)
  rect 1.499x2.743 smd: 8(-2.375,-2.4) 9(7.825,-2.4)
